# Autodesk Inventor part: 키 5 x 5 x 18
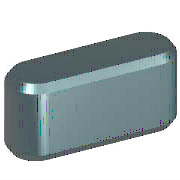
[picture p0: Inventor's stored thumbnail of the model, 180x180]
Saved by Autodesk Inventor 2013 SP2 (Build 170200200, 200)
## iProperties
Created: 2012-02
Part Number: 키 5 x 5 x 18
Material: 강철, 연강
Description: 키 및 해당 키홈
Document SubType Name: Modeling
Standard: KS B 1311
Designer: mduedu
Standards Organization: KS
Language: ko-KR
Size Designation: 5 x 5 x 18
Categories: <MemberInstance><Categories><Category DisplayName="샤프트 부품" InternalName="7f7aeb1f-a693-4053-b835-cee3144e0d98" Mnemonic="SHFT"><Category DisplayName="키" Interna
Density: 1 g/cm^3
IsCustomPart: 1
Author: mduedu
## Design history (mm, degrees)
workplane "Work Plane1"
workplane "Work Plane2"
sketch "스케치1"
  geometry: L1 (2.5, 2.5)-(15.5, 2.5); L2 (15.5, -2.5)-(2.5, -2.5); L3 (0, 9.4)-(0, -7.4) reference; L4 (-5, 0)-(30, 0) reference; L5 (18, 0)-(18, 7); A1 r 2.5 centre (2.5, 0) between (2.5, 2.5) and (2.5, -2.5); A2 r 2.5 centre (15.5, 0) between (15.5, -2.5) and (15.5, 2.5)
  constraints: 6 end point, 5 point on circle, 4 tangent, 3 point on line, 2 centre point, 1 horizontal, 1 parallel, 1 perpendicular
  dimensions: "d0" = 2.5 radius of A1 (= 0.5 x PB); "d13" = 2.5 radius of A2 (= 0.5 x PB); "d14" = 18 distance between parallel lines of L5 L3 (= NLG)
extrude "본체1" new body sketch "스케치1" taper "d3" = 0 deg; stored distance "d4" = 10
workplane "Work Plane3"
body "Solid1"
chamfer "모따기1" distance "d8" = 0.4 (= PHH); stored, may be unused: second distance "d9" = 0.4 (= PHH), angle "d15" = 45 deg
other parameters: "d1" = -3 (= -PNT), "d2" = 2 (= PH - PNT), "NLG" = 18 [user parameter; used in 3 equation terms], "PB" = 5 [user parameter; used in 2 equation terms], "PNT" = 3 [user parameter; used in 2 equation terms], "PH" = 5 [user parameter; used in 1 equation term], "PHH" = 0.4 [user parameter; used in 2 equation terms], "d10" = 0, "d16" = 0, "d17" = 0, "d18" = 0, "WDMIN" = 12 [user parameter], "PLB2" = 18 (= NLG) [user parameter], "WDMAX" = 17 [user parameter], "PLB1" = 18 (= NLG) [user parameter], "RR" = 0.16 [user parameter], "PUEB" = 2.3 [user parameter]
